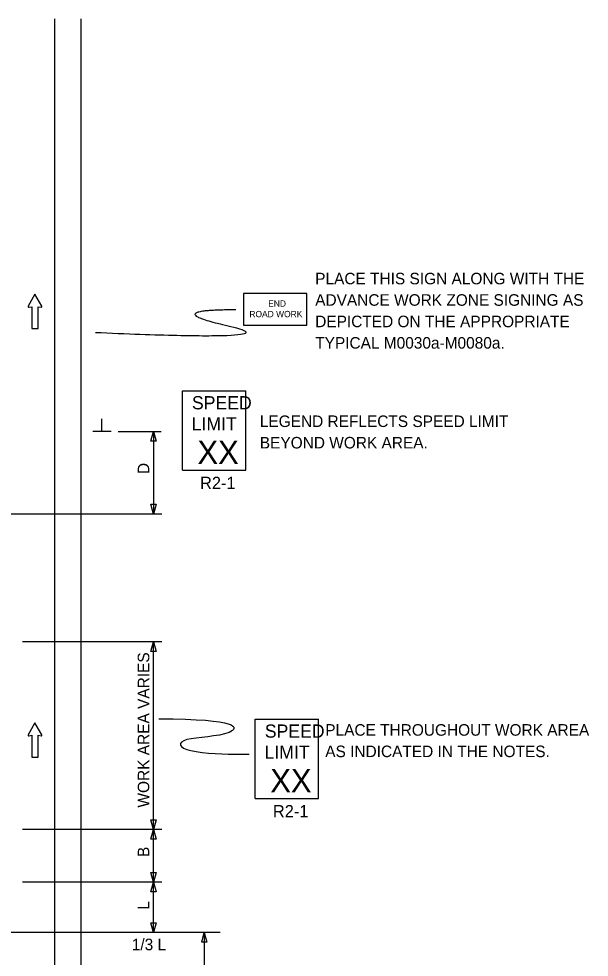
# Model space of a CAD drawing. Extents: x 16731 to 18475, y 5706 to 6928.
# Drawn here: x 17062 to 17408, y 6357 to 6926 of the extents above; entities that cross this region are included whole.
import ezdxf

# ---------------------------------------------------------------- set-up
doc = ezdxf.new("R2010")
doc.units = 0
for name, color, linetype in [('MT_SCRATCH_LEVEL_E', 7, 'Continuous'), ('PAVT_EDGE_EX', 7, 'Continuous'), ('TRAFFIC_SIGNS_PR', 7, 'Continuous'), ('TYPICAL_TEXT_DIMEN_PR', 7, 'Continuous')]:
    doc.layers.add(name, color=color, linetype=linetype)

msp = doc.modelspace()

# ---------------------------------------------------------------- linework, layer by layer
at = {"layer": 'MT_SCRATCH_LEVEL_E'}
for p, q in [((17071.54, 6759.44), (17067.43, 6752.2)), ((17071.54, 6759.44), (17067.43, 6752.2)), ((17075.69, 6752.2), (17071.54, 6759.44)), ((17075.69, 6752.2), (17071.54, 6759.44)), ((17067.91, 6751.51), (17069.69, 6751.83)), ((17067.91, 6751.51), (17069.69, 6751.83)), ((17069.69, 6751.83), (17069.69, 6738.57)), ((17069.69, 6751.83), (17069.69, 6738.57)), ((17073.43, 6738.57), (17073.43, 6751.83)), ((17073.43, 6751.83), (17075.21, 6751.51)), ((17073.43, 6738.57), (17073.43, 6751.83)), ((17073.43, 6751.83), (17075.21, 6751.51)), ((17069.69, 6738.57), (17073.43, 6738.57)), ((17069.69, 6738.57), (17073.43, 6738.57)), ((17071.54, 6499.51), (17067.43, 6492.27)), ((17071.54, 6499.51), (17067.43, 6492.27)), ((17075.69, 6492.27), (17071.54, 6499.51)), ((17075.69, 6492.27), (17071.54, 6499.51)), ((17067.91, 6491.59), (17069.69, 6491.9)), ((17067.91, 6491.59), (17069.69, 6491.9)), ((17069.69, 6491.9), (17069.69, 6478.65)), ((17069.69, 6491.9), (17069.69, 6478.65)), ((17073.43, 6478.65), (17073.43, 6491.9)), ((17073.43, 6491.9), (17075.21, 6491.59)), ((17073.43, 6478.65), (17073.43, 6491.9)), ((17073.43, 6491.9), (17075.21, 6491.59)), ((17069.69, 6478.65), (17073.43, 6478.65)), ((17069.69, 6478.65), (17073.43, 6478.65))]:
    msp.add_line(p, q, dxfattribs=at)
for centre, start, end in [((17067.84, 6751.97), 150.4248, 279.9638), ((17067.84, 6751.97), 150.4248, 279.9638), ((17075.28, 6751.97), 260.0362, 29.7731), ((17075.28, 6751.97), 260.0362, 29.7731), ((17067.84, 6492.05), 150.4248, 279.9638), ((17067.84, 6492.05), 150.4248, 279.9638), ((17075.28, 6492.05), 260.0362, 29.7731), ((17075.28, 6492.05), 260.0362, 29.7731)]:
    msp.add_arc(centre, 0.463, start, end, dxfattribs=at)
at = {"layer": 'PAVT_EDGE_EX'}
for p, q in [((17083.43, 6926.45), (17083.43, 6059.71)), ((17099.43, 6926.45), (17099.43, 6059.71))]:
    msp.add_line(p, q, dxfattribs=at)
at = {"layer": 'TRAFFIC_SIGNS_PR'}
for p, q in [((17161, 6700.73), (17199.4, 6700.73)), ((17161, 6652.73), (17161, 6700.73)), ((17199.4, 6652.73), (17199.4, 6700.73)), ((17161, 6652.73), (17199.4, 6652.73)), ((17205.21, 6501.62), (17243.61, 6501.62)), ((17205.21, 6453.62), (17205.21, 6501.62)), ((17243.61, 6453.62), (17243.61, 6501.62)), ((17205.21, 6453.62), (17243.61, 6453.62))]:
    msp.add_line(p, q, dxfattribs=at)
msp.add_lwpolyline([(17198.01, 6740.73), (17236.41, 6740.73), (17236.41, 6759.93), (17198.01, 6759.93)], close=True, dxfattribs=at)
msp.add_open_spline([(17193.47, 6749.91), (17146.24, 6749.91), (17231.26, 6730.56), (17108.16, 6736.05)], degree=2, dxfattribs=at)
at = {"layer": 'TYPICAL_TEXT_DIMEN_PR'}
for p, q in [((17112.19, 6676.12), (17112.19, 6683.91)), ((17117.82, 6676.12), (17106.57, 6676.12)), ((17122.07, 6676.12), (17148.07, 6676.12)), ((17141.86, 6670.26), (17143.43, 6676.12)), ((17143.43, 6676.12), (17143.43, 6626.12)), ((17143.43, 6676.12), (17145, 6670.26)), ((17143.43, 6670.26), (17141.86, 6670.26)), ((17145, 6670.26), (17143.43, 6670.26)), ((17143.43, 6626.12), (17141.86, 6631.99)), ((17141.86, 6631.99), (17143.43, 6631.99)), ((17143.43, 6631.99), (17145, 6631.99)), ((17145, 6631.99), (17143.43, 6626.12)), ((17148.43, 6626.12), (17046.02, 6626.12)), ((17148.43, 6548.61), (17063.94, 6548.61)), ((17141.86, 6542.75), (17143.43, 6548.61)), ((17143.43, 6434.88), (17143.43, 6548.61)), ((17143.43, 6548.61), (17145, 6542.75)), ((17143.43, 6542.75), (17141.86, 6542.75)), ((17145, 6542.75), (17143.43, 6542.75)), ((17195.3, 6480.47), (17201.57, 6480.47)), ((17143.43, 6434.88), (17141.86, 6440.75)), ((17141.86, 6440.75), (17143.43, 6440.75)), ((17143.43, 6440.75), (17145, 6440.75)), ((17145, 6440.75), (17143.43, 6434.88)), ((17148.43, 6434.88), (17063.94, 6434.88)), ((17141.86, 6429.02), (17143.43, 6434.88)), ((17143.43, 6402.82), (17143.43, 6434.88)), ((17143.43, 6434.88), (17145, 6429.02)), ((17143.43, 6429.02), (17141.86, 6429.02)), ((17145, 6429.02), (17143.43, 6429.02)), ((17143.43, 6402.82), (17141.86, 6408.69)), ((17141.86, 6408.69), (17143.43, 6408.69)), ((17143.43, 6408.69), (17145, 6408.69)), ((17145, 6408.69), (17143.43, 6402.82)), ((17148.43, 6402.82), (17063.94, 6402.82)), ((17141.86, 6396.96), (17143.43, 6402.82)), ((17143.43, 6402.82), (17145, 6396.96)), ((17143.43, 6372.25), (17143.43, 6402.82)), ((17143.43, 6396.96), (17141.86, 6396.96)), ((17145, 6396.96), (17143.43, 6396.96)), ((17143.43, 6372.25), (17141.86, 6378.11)), ((17141.86, 6378.11), (17143.43, 6378.11)), ((17143.43, 6378.11), (17145, 6378.11)), ((17145, 6378.11), (17143.43, 6372.25)), ((17183.8, 6372.25), (17042.79, 6372.25)), ((17172.71, 6366.39), (17174.28, 6372.25)), ((17174.28, 6372.25), (17175.85, 6366.39)), ((17174.28, 6372.25), (17174.28, 6322.25)), ((17174.28, 6366.39), (17172.71, 6366.39)), ((17175.85, 6366.39), (17174.28, 6366.39))]:
    msp.add_line(p, q, dxfattribs=at)
for points, degree in [([(17146.75, 6501.92), (17195.73, 6501.92), (17195.73, 6490.92), (17156.87, 6490.92), (17159.38, 6481.18), (17188.11, 6480.49), (17195.3, 6480.47)], 3), ([(17223.31, 6481), (17223.32, 6481), (17223.32, 6481), (17223.32, 6481)], 2)]:
    msp.add_open_spline(points, degree=degree, dxfattribs=at)

# ---------------------------------------------------------------- texts
at = {"layer": 'TRAFFIC_SIGNS_PR'}
for s, height, p in [('PLACE THIS SIGN ALONG WITH THE', 7, (17241.56, 6765.41)), ('END', 3.831, (17213.01, 6751.86)), ('ADVANCE WORK ZONE SIGNING AS', 7, (17241.56, 6752.41)), ('ROAD WORK', 3.831, (17201.62, 6745.47)), ('DEPICTED ON THE APPROPRIATE', 7, (17241.56, 6739.41)), ('TYPICAL M0030a-M0080a.', 7, (17241.56, 6726.41)), ('SPEED', 8, (17166.77, 6689.59)), ('LIMIT', 8, (17166.61, 6676.79)), ('LEGEND REFLECTS SPEED LIMIT', 7, (17207.95, 6678.87)), ('XX', 14.031, (17170.12, 6656.49)), ('BEYOND WORK AREA.', 7, (17207.95, 6665.87)), ('R2-1', 7.44, (17171.68, 6641.29)), ('SPEED', 8, (17210.98, 6490.48)), ('PLACE THROUGHOUT WORK AREA', 7, (17247.66, 6491.67)), ('LIMIT', 8, (17210.81, 6477.68)), ('AS INDICATED IN THE NOTES.', 7, (17247.66, 6478.67)), ('XX', 14.031, (17214.32, 6457.38)), ('R2-1', 7.44, (17215.88, 6442.18))]:
    msp.add_text(s, height=height, dxfattribs=at).set_placement(p)
at = {"layer": 'TYPICAL_TEXT_DIMEN_PR'}
for s, p in [('D', (17140.88, 6650.34)), ('WORK AREA VARIES', (17140.88, 6448.1)), ('B', (17140.88, 6418.09)), ('L', (17140.88, 6386.12))]:
    msp.add_text(s, height=7, rotation=90, dxfattribs=at).set_placement(p)
msp.add_text('1/3 L', height=7, dxfattribs=at).set_placement((17130.28, 6361.57))

doc.saveas('drawing.dxf')
